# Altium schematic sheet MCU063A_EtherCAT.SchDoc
size 431 x 279 mm; Date: Not shown in title block; ApprovedBy: Not shown in title block; CheckedBy: Not shown in title block; Author: Not shown in title block; CompanyName: Not shown in title block; Engineer: Not shown in title block; Organization: Not shown in title block; Address1: Not shown in title block; Address2: Not shown in title block; Address3: Not shown in title block; Address4: Not shown in title block; DocumentNumber: 8; Revision: Use project parameter SCH_Rev; SheetNumber: 8; SheetTotal: 11; PageSetup: Record=PageOptions¦CenterHorizontal=True¦CenterVertical=True¦PrintScale=1.00¦XCorrection=1.00¦YCorrection=1.00¦PrintKind=0¦BorderSize=5000000¦LeftOffset=0¦BottomOffset=0¦Orientation=2¦PaperLength=1000¦PaperWidth=1000¦Scale=100¦PaperSource=15¦PrintQuality=600¦MediaType=1¦DitherType=10¦PaperKind=Letter¦PrintScaleMode=1
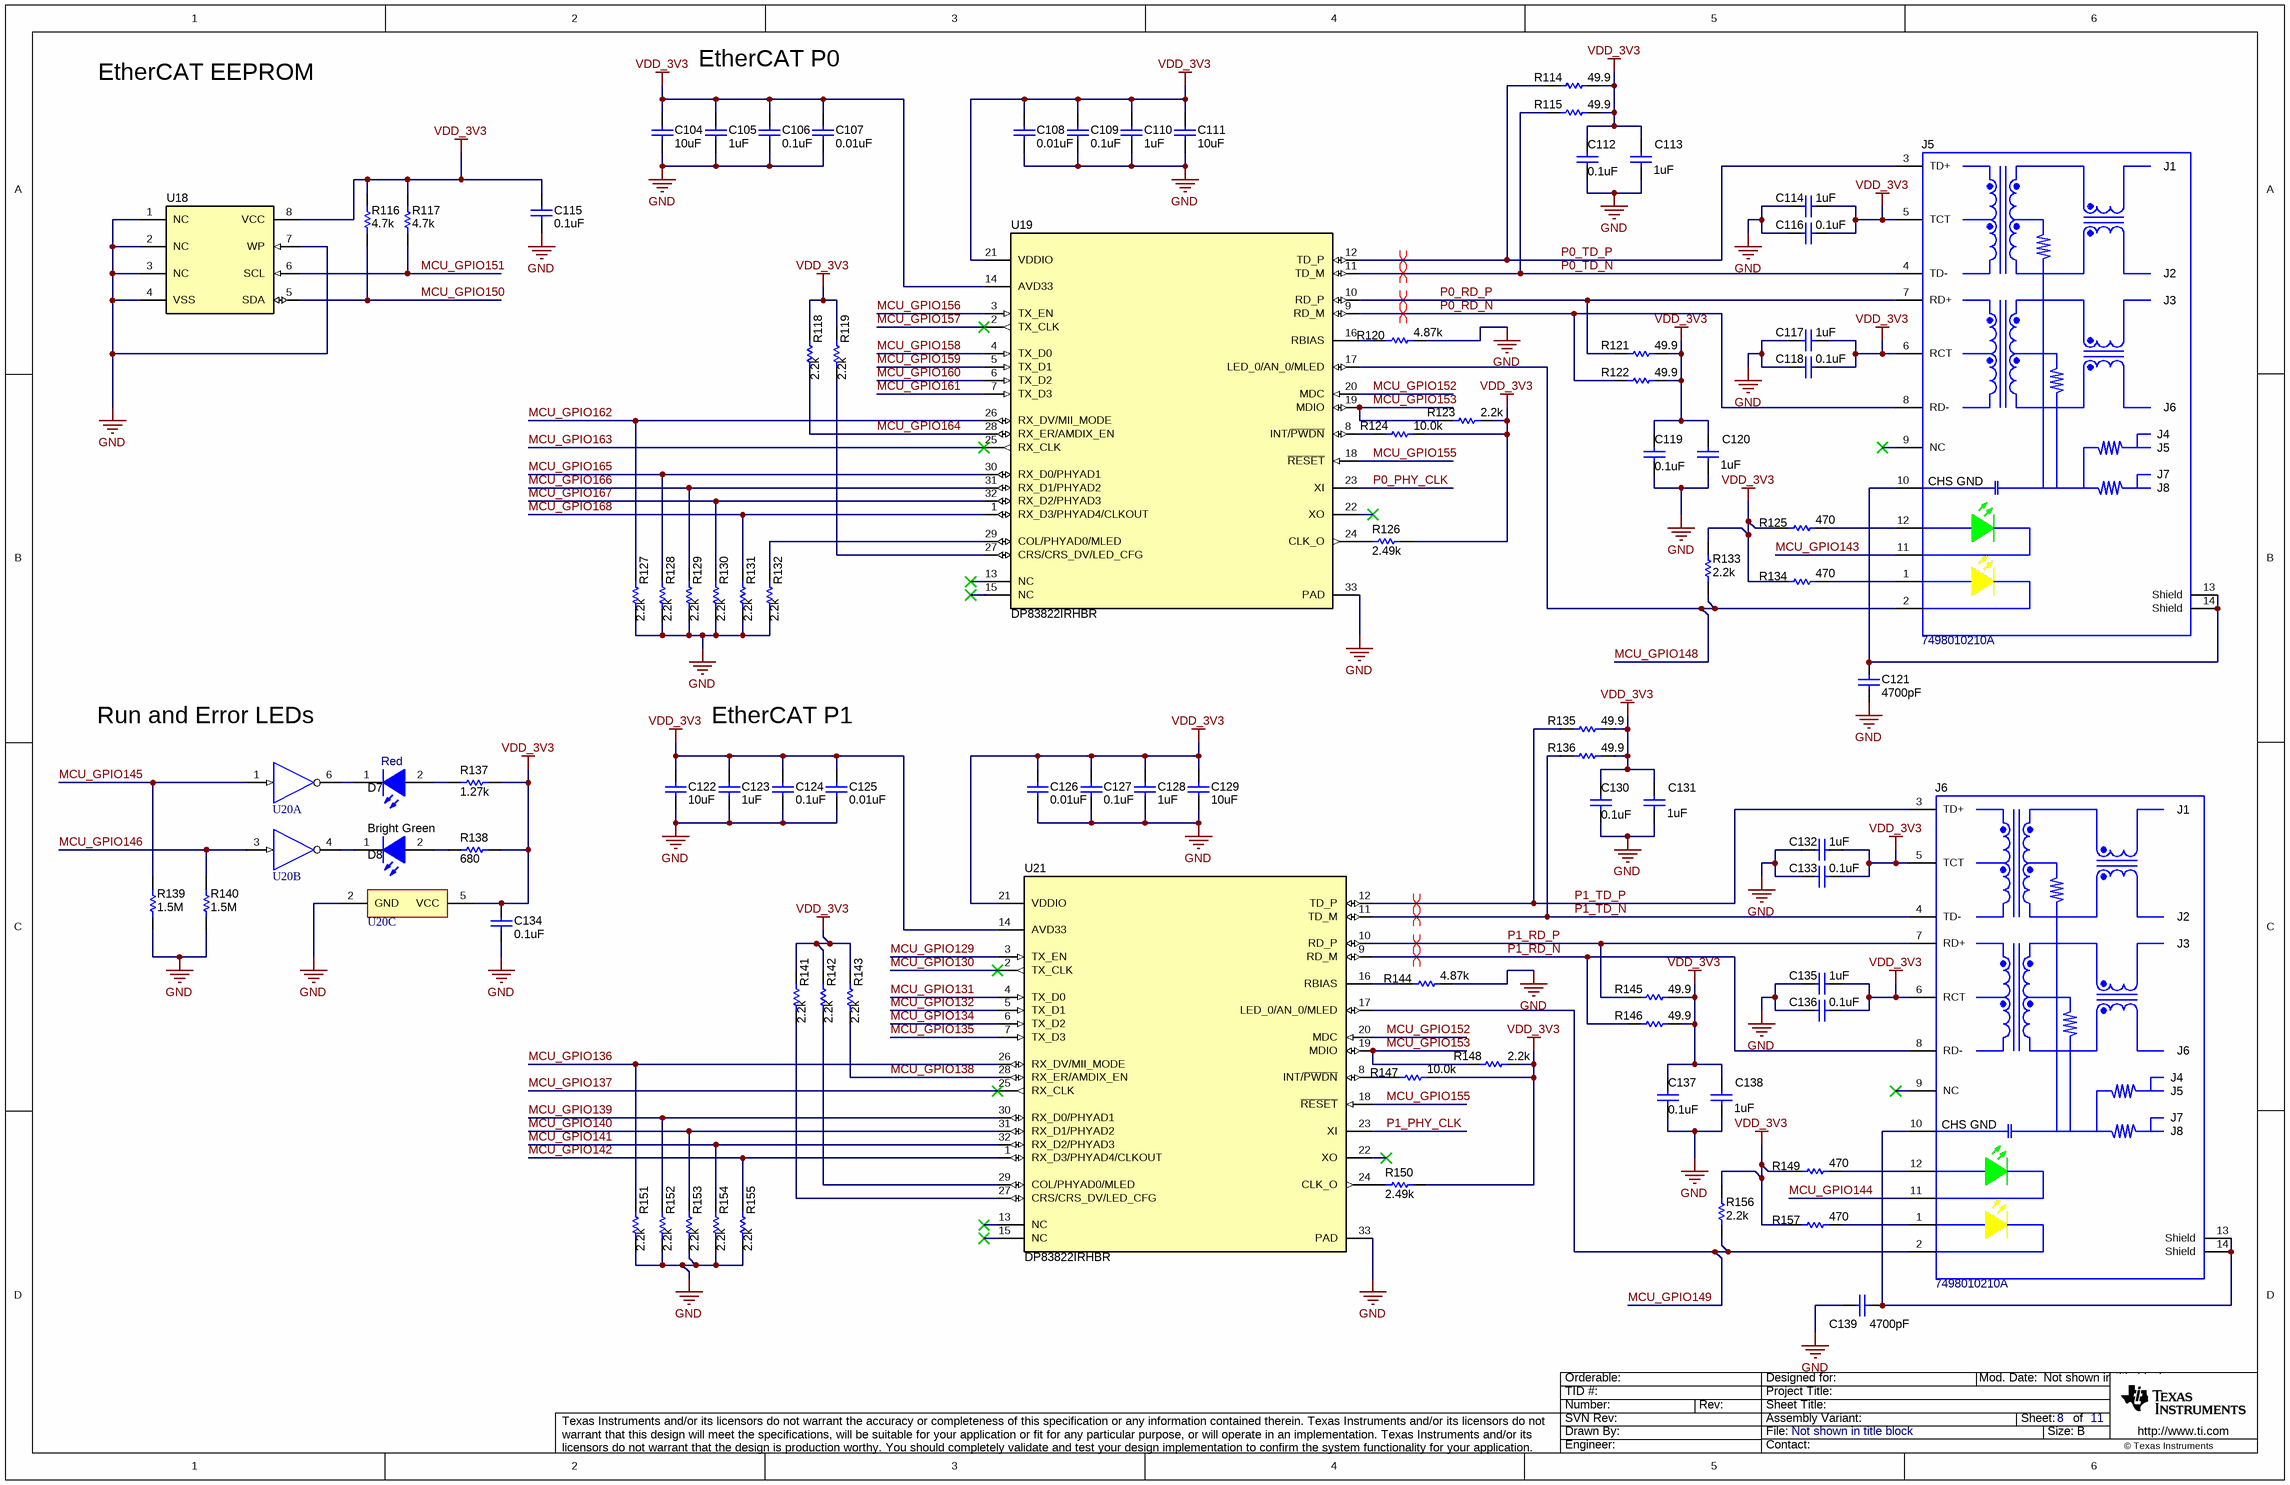
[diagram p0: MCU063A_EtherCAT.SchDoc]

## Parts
C104  ValueDisplayed: 10uF  [0402]  (hidden comment: CL05A106MQ5NUNC)
C105  ValueDisplayed: 1uF  [0402]  (hidden comment: EMK105BJ105KVHF)
C106  ValueDisplayed: 0.1uF  [0402]  (hidden comment: LMK105BJ104KV-F)
C107  ValueDisplayed: 0.01uF  [0402]  (hidden comment: 885012205031)
C108  ValueDisplayed: 0.01uF  [0402]  (hidden comment: 885012205031)
C109  ValueDisplayed: 0.1uF  [0402]  (hidden comment: LMK105BJ104KV-F)
C110  ValueDisplayed: 1uF  [0402]  (hidden comment: EMK105BJ105KVHF)
C111  ValueDisplayed: 10uF  [0402]  (hidden comment: CL05A106MQ5NUNC)
C112  ValueDisplayed: 0.1uF  [0402]  (hidden comment: LMK105BJ104KV-F)
C113  ValueDisplayed: 1uF  [0402]  (hidden comment: EMK105BJ105KVHF)
C114  ValueDisplayed: 1uF  [0402]  (hidden comment: EMK105BJ105KVHF)
C115  ValueDisplayed: 0.1uF  [0402]  (hidden comment: CL05B104KP5NNNC)
C116  ValueDisplayed: 0.1uF  [0402]  (hidden comment: LMK105BJ104KV-F)
C117  ValueDisplayed: 1uF  [0402]  (hidden comment: EMK105BJ105KVHF)
C118  ValueDisplayed: 0.1uF  [0402]  (hidden comment: LMK105BJ104KV-F)
C119  ValueDisplayed: 0.1uF  [0402]  (hidden comment: LMK105BJ104KV-F)
C120  ValueDisplayed: 1uF  [0402]  (hidden comment: EMK105BJ105KVHF)
C121  ValueDisplayed: 4700pF  [1206]  (hidden comment: 12061C472KAT2A)
C122  ValueDisplayed: 10uF  [0402]  (hidden comment: CL05A106MQ5NUNC)
C123  ValueDisplayed: 1uF  [0402]  (hidden comment: EMK105BJ105KVHF)
C124  ValueDisplayed: 0.1uF  [0402]  (hidden comment: LMK105BJ104KV-F)
C125  ValueDisplayed: 0.01uF  [0402]  (hidden comment: 885012205031)
C126  ValueDisplayed: 0.01uF  [0402]  (hidden comment: 885012205031)
C127  ValueDisplayed: 0.1uF  [0402]  (hidden comment: LMK105BJ104KV-F)
C128  ValueDisplayed: 1uF  [0402]  (hidden comment: EMK105BJ105KVHF)
C129  ValueDisplayed: 10uF  [0402]  (hidden comment: CL05A106MQ5NUNC)
C130  ValueDisplayed: 0.1uF  [0402]  (hidden comment: LMK105BJ104KV-F)
C131  ValueDisplayed: 1uF  [0402]  (hidden comment: EMK105BJ105KVHF)
C132  ValueDisplayed: 1uF  [0402]  (hidden comment: EMK105BJ105KVHF)
C133  ValueDisplayed: 0.1uF  [0402]  (hidden comment: LMK105BJ104KV-F)
C134  ValueDisplayed: 0.1uF  [0402]  (hidden comment: CL05B104KP5NNNC)
C135  ValueDisplayed: 1uF  [0402]  (hidden comment: EMK105BJ105KVHF)
C136  ValueDisplayed: 0.1uF  [0402]  (hidden comment: LMK105BJ104KV-F)
C137  ValueDisplayed: 0.1uF  [0402]  (hidden comment: LMK105BJ104KV-F)
C138  ValueDisplayed: 1uF  [0402]  (hidden comment: EMK105BJ105KVHF)
C139  ValueDisplayed: 4700pF  [1206]  (hidden comment: 12061C472KAT2A)
D7  value Red  [WL-SMCW_RED_0805]  (hidden comment: 150080SS75000)
D8  value Bright Green  [WL-SMCW_Green_0805]  (hidden comment: 150080VS75000)
J5  7498010210A  [Wurth_7498010210A]
J6  7498010210A  [Wurth_7498010210A]
R114  ValueDisplayed: 49.9  [0402]  (hidden comment: RC0402FR-0749R9L)
R115  ValueDisplayed: 49.9  [0402]  (hidden comment: RC0402FR-0749R9L)
R116  ValueDisplayed: 4.7k  [0402]  (hidden comment: CRCW04024K70JNED)
R117  ValueDisplayed: 4.7k  [0402]  (hidden comment: CRCW04024K70JNED)
R118  ValueDisplayed: 2.2k  [0201]  (hidden comment: CRCW02012K20JNED)
R119  ValueDisplayed: 2.2k  [0201]  (hidden comment: CRCW02012K20JNED)
R120  ValueDisplayed: 4.87k  [0402]  (hidden comment: CRCW04024K87FKED)
R121  ValueDisplayed: 49.9  [0402]  (hidden comment: RC0402FR-0749R9L)
R122  ValueDisplayed: 49.9  [0402]  (hidden comment: RC0402FR-0749R9L)
R123  ValueDisplayed: 2.2k  [0402]  (hidden comment: CRCW04022K20JNED)
R124  ValueDisplayed: 10.0k  [0402]  (hidden comment: RC0402FR-0710KL)
R125  ValueDisplayed: 470  [0603]  (hidden comment: CRCW0603470RJNEA)
R126  ValueDisplayed: 2.49k  [0402]  (hidden comment: CRCW04022K49FKED)
R127  ValueDisplayed: 2.2k  [0201]  (hidden comment: CRCW02012K20JNED)
R128  ValueDisplayed: 2.2k  [0201]  (hidden comment: CRCW02012K20JNED)
R129  ValueDisplayed: 2.2k  [0201]  (hidden comment: CRCW02012K20JNED)
R130  ValueDisplayed: 2.2k  [0201]  (hidden comment: CRCW02012K20JNED)
R131  ValueDisplayed: 2.2k  [0201]  (hidden comment: CRCW02012K20JNED)
R132  ValueDisplayed: 2.2k  [0201]  (hidden comment: CRCW02012K20JNED)
R133  ValueDisplayed: 2.2k  [0402]  (hidden comment: CRCW04022K20JNED)
R134  ValueDisplayed: 470  [0603]  (hidden comment: CRCW0603470RJNEA)
R135  ValueDisplayed: 49.9  [0402]  (hidden comment: RC0402FR-0749R9L)
R136  ValueDisplayed: 49.9  [0402]  (hidden comment: RC0402FR-0749R9L)
R137  ValueDisplayed: 1.27k  [0402]  (hidden comment: CRCW04021K27FKED)
R138  ValueDisplayed: 680  [0402]  (hidden comment: CRCW0402680RJNED)
R139  ValueDisplayed: 1.5M  [0402]  (hidden comment: CRCW04021M50JNED)
R140  ValueDisplayed: 1.5M  [0402]  (hidden comment: CRCW04021M50JNED)
R141  ValueDisplayed: 2.2k  [0201]  (hidden comment: CRCW02012K20JNED)
R142  ValueDisplayed: 2.2k  [0201]  (hidden comment: CRCW02012K20JNED)
R143  ValueDisplayed: 2.2k  [0201]  (hidden comment: CRCW02012K20JNED)
R144  ValueDisplayed: 4.87k  [0402]  (hidden comment: CRCW04024K87FKED)
R145  ValueDisplayed: 49.9  [0402]  (hidden comment: RC0402FR-0749R9L)
R146  ValueDisplayed: 49.9  [0402]  (hidden comment: RC0402FR-0749R9L)
R147  ValueDisplayed: 10.0k  [0402]  (hidden comment: RC0402FR-0710KL)
R148  ValueDisplayed: 2.2k  [0402]  (hidden comment: CRCW04022K20JNED)
R149  ValueDisplayed: 470  [0603]  (hidden comment: CRCW0603470RJNEA)
R150  ValueDisplayed: 2.49k  [0402]  (hidden comment: CRCW04022K49FKED)
R151  ValueDisplayed: 2.2k  [0201]  (hidden comment: CRCW02012K20JNED)
R152  ValueDisplayed: 2.2k  [0201]  (hidden comment: CRCW02012K20JNED)
R153  ValueDisplayed: 2.2k  [0201]  (hidden comment: CRCW02012K20JNED)
R154  ValueDisplayed: 2.2k  [0201]  (hidden comment: CRCW02012K20JNED)
R155  ValueDisplayed: 2.2k  [0201]  (hidden comment: CRCW02012K20JNED)
R156  ValueDisplayed: 2.2k  [0402]  (hidden comment: CRCW04022K20JNED)
R157  ValueDisplayed: 470  [0603]  (hidden comment: CRCW0603470RJNEA)
U18  CAT24C16WI-GT3  [SOIC-8]  (value not drawn)
U19  DP83822IRHBR  [RHB0032B]
U20  SN74LVC2G06DBVR  [DBV0006A_N]  (value not drawn)  (parts A,B,C of 3)
U21  DP83822IRHBR  [RHB0032B]

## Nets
GND: C104.2 C105.2 C106.2 C107.2 C108.2 C109.2 C110.2 C111.2 C112.2 C113.2 C114.1 C115.2 C116.1 C117.1 C118.1 C119.2 C120.2 C121.1 C122.2 C123.2 C124.2 C125.2 C126.2 C127.2 C128.2 C129.2 C130.2 C131.2 C132.1 C133.1 C134.2 C135.1 C136.1 C137.2 C138.2 C139.1 R120.2 R127.1 R128.1 R129.1 R130.1 R131.1 R132.1 R139.2 R140.2 R144.2 R151.1 R152.1 R153.1 R154.1 R155.1 U18.1(NC) U18.2(NC) U18.3(NC) U18.4(VSS) U18.7(WP) U19.33(PAD) U20.2(GND) U21.33(PAD)
VDD_3V3: C104.1 C105.1 C106.1 C107.1 C108.1 C109.1 C110.1 C111.1 C112.1 C113.1 C114.2 C115.1 C116.2 C117.2 C118.2 C119.1 C120.1 C122.1 C123.1 C124.1 C125.1 C126.1 C127.1 C128.1 C129.1 C130.1 C131.1 C132.2 C133.2 C134.1 C135.2 C136.2 C137.1 C138.1 J5.5(TCT) J5.6(RCT) J6.5(TCT) J6.6(RCT) R114.2 R115.2 R116.2 R117.2 R118.2 R119.2 R121.2 R122.2 R123.1 R124.2 R125.1 R126.1 R133.2 R134.1 R135.2 R136.2 R137.2 R138.1 R141.2 R142.2 R143.2 R145.2 R146.2 R147.2 R148.1 R149.1 R150.1 R156.2 R157.1 U18.8(VCC) U19.14(AVD33) U19.21(VDDIO) U20.5(VCC) U21.14(AVD33) U21.21(VDDIO)
MCU_GPIO129: U21.3(TX_EN)
MCU_GPIO130: U21.2(TX_CLK)
MCU_GPIO131: U21.4(TX_D0)
MCU_GPIO132: U21.5(TX_D1)
MCU_GPIO134: U21.6(TX_D2)
MCU_GPIO135: U21.7(TX_D3)
MCU_GPIO136: R151.2 U21.26(RX_DV/MII_MODE)
MCU_GPIO137: U21.25(RX_CLK)
MCU_GPIO138: R143.1 U21.28(RX_ER/AMDIX_EN)
MCU_GPIO139: R152.2 U21.30(RX_D0/PHYAD1)
MCU_GPIO140: R153.2 U21.31(RX_D1/PHYAD2)
MCU_GPIO141: R154.2 U21.32(RX_D2/PHYAD3)
MCU_GPIO142: R155.2 U21.1(RX_D3/PHYAD4/CLKOUT)
MCU_GPIO143: J5.11(LEFT_LED_CATHODE)
MCU_GPIO144: J6.11(LEFT_LED_CATHODE)
MCU_GPIO145: R139.1 U20.1(1A)
MCU_GPIO146: R140.1 U20.3(2A)
MCU_GPIO148: J5.2(RIGHT_LED_CATHODE) R133.1 U19.17(LED_0/AN_0/MLED)
MCU_GPIO149: J6.2(RIGHT_LED_CATHODE) R156.1 U21.17(LED_0/AN_0/MLED)
MCU_GPIO150: R116.1 U18.5(SDA)
MCU_GPIO151: R117.1 U18.6(SCL)
MCU_GPIO152: U19.20(MDC) U21.20(MDC)
MCU_GPIO153: R123.2 R148.2 U19.19(MDIO) U21.19(MDIO)
MCU_GPIO155: U19.18(~{RESET}) U21.18(~{RESET})
MCU_GPIO156: U19.3(TX_EN)
MCU_GPIO157: U19.2(TX_CLK)
MCU_GPIO158: U19.4(TX_D0)
MCU_GPIO159: U19.5(TX_D1)
MCU_GPIO160: U19.6(TX_D2)
MCU_GPIO161: U19.7(TX_D3)
MCU_GPIO162: R127.2 U19.26(RX_DV/MII_MODE)
MCU_GPIO163: U19.25(RX_CLK)
MCU_GPIO164: R118.1 U19.28(RX_ER/AMDIX_EN)
MCU_GPIO165: R128.2 U19.30(RX_D0/PHYAD1)
MCU_GPIO166: R129.2 U19.31(RX_D1/PHYAD2)
MCU_GPIO167: R130.2 U19.32(RX_D2/PHYAD3)
MCU_GPIO168: R131.2 U19.1(RX_D3/PHYAD4/CLKOUT)
P0_PHY_CLK: U19.23(XI)
P0_RD_N: J5.8(RD-) R122.1 U19.9(RD_M)
P0_RD_P: J5.7(RD+) R121.1 U19.10(RD_P)
P0_TD_N: J5.4(TD-) R115.1 U19.11(TD_M)
P0_TD_P: J5.3(TD+) R114.1 U19.12(TD_P)
P1_PHY_CLK: U21.23(XI)
P1_RD_N: J6.8(RD-) R146.1 U21.9(RD_M)
P1_RD_P: J6.7(RD+) R145.1 U21.10(RD_P)
P1_TD_N: J6.4(TD-) R136.1 U21.11(TD_M)
P1_TD_P: J6.3(TD+) R135.1 U21.12(TD_P)
NetC121_2: C121.2 J5.10(CHS_GND) J5.13(Shield) J5.14(Shield)
NetC139_2: C139.2 J6.10(CHS_GND) J6.13(Shield) J6.14(Shield)
NetD7_1: D7.1(K) U20.6(1Y)
NetD7_2: D7.2(A) R137.1
NetD8_1: D8.1(K) U20.4(2Y)
NetD8_2: D8.2(A) R138.2
NetJ5_1: J5.1(RIGHT_LED_ANODE) R134.2
NetJ5_12: J5.12(LEFT_LED_ANODE) R125.2
NetJ6_1: J6.1(RIGHT_LED_ANODE) R157.2
NetJ6_12: J6.12(LEFT_LED_ANODE) R149.2
NetR119_1: R119.1 U19.27(CRS/CRS_DV/LED_CFG)
NetR120_1: R120.1 U19.16(RBIAS)
NetR124_1: R124.1 U19.8(INT/~{PWDN})
NetR126_2: R126.2 U19.24(CLK_O)
NetR132_2: R132.2 U19.29(COL/PHYAD0/MLED)
NetR141_1: R141.1 U21.27(CRS/CRS_DV/LED_CFG)
NetR142_1: R142.1 U21.29(COL/PHYAD0/MLED)
NetR144_1: R144.1 U21.16(RBIAS)
NetR147_1: R147.1 U21.8(INT/~{PWDN})
NetR150_2: R150.2 U21.24(CLK_O)

Not connected (* = marked no-connect by the designer): J5 9(NC)*; J6 9(NC)*; U19 13(NC)* 15(NC)* 22(XO)*; U21 13(NC)* 15(NC)* 22(XO)*

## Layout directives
differential pair: P0_RD_N, P0_RD_P, P0_TD_N, P0_TD_P, P1_RD_N, P1_RD_P, P1_TD_N, P1_TD_P

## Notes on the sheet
- EtherCAT EEPROM
- EtherCAT P0
- Run and Error LEDs
- EtherCAT P1

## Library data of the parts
C104 C111 C122 C129 = CMP-0006340-2: CAP, CERM, 10 uF, 6.3 V, +/- 20%, X5R, 0402; Manufacturer: Samsung Electro-Mechanics; TaMin_C: -55°C; Polarized: N; SizeAreaWB_mm2: 3; Value1: Unknown; U/M: EA; Value: 10uF; TaMax_C: 85°C; SizeZ_mm: 0.6; SizeX_mm: 1; SizeY_mm: 0.5; Value2: 6.3V; Cap_F: 10µF; AEC Category: Q200
C105 C110 C113 C114 C117 C120 C123 C128 C131 C132 C135 C138 = CMP-0006347-2: CAP, CERM, 1 uF, 16 V, +/- 10%, X5R, 0402; Manufacturer: Taiyo Yuden; TaMin_C: -55°C; Polarized: N; SizeAreaWB_mm2: 3; Value1: Unknown; U/M: EA; Value: 1uF; TaMax_C: 85°C; SizeZ_mm: 0.6; SizeX_mm: 1; SizeY_mm: 0.5; Value2: 16V; Cap_F: 1µF; AEC Category: Q200
C106 C109 C112 C116 C118 C119 C124 C127 C130 C133 C136 C137 = CMP-0064930-2: CAP, CERM, 0.1 uF, 10 V,+/- 10%, X5R, 0402; Manufacturer: Taiyo Yuden; TaMin_C: -55°C; Polarized: N; SizeAreaWB_mm2: 3; Value1: Unknown; U/M: EA; Value: 0.1uF; TaMax_C: 85°C; SizeZ_mm: 0.6; SizeX_mm: 1; SizeY_mm: 0.5; Value2: 10V; Cap_F: 100nF; AEC Category: Q200
C107 C108 C125 C126 = CMP-0006227-2: CAP, CERM, 0.01 uF, 16 V, +/- 10%, X7R, 0402; Manufacturer: Wurth Elektronik; TaMin_C: -55°C; Polarized: N; SizeAreaWB_mm2: 3; Value1: Unknown; U/M: EA; Value: 0.01uF; TaMax_C: 125°C; SizeZ_mm: 0.6; SizeX_mm: 1; SizeY_mm: 0.5; Value2: 16V; Cap_F: 10nF; AEC Category: Q200
C115 C134 = CMP-0006343-2: CAP, CERM, 0.1 uF, 10 V, +/- 10%, X7R, 0402; Manufacturer: Samsung Electro-Mechanics; Polarized: N; Value: 0.1uF; U/M: EA; Cap_F: 100nF; Value1: Unknown; VDC_V: 10V; TaMin_C: -55°C; TaMax_C: 125°C; AEC Category: Q200; SizeArea_mm2: 0.5; SizeAreaWB_mm2: 3; SizeX_mm: 1; SizeZ_mm: 0.6
C121 C139 = CMP-0008501-2: CAP, CERM, 4700 pF, 100 V, +/- 10%, X7R, 1206; Manufacturer: AVX; TaMin_C: -55°C; ESR_ohm: 1.78d; Polarized: N; SizeAreaWB_mm2: 10.92; Value1: 0.178 ohm; U/M: EA; Value: 4700pF; TaMax_C: 125°C; SizeZ_mm: 1.35; SizeX_mm: 3.2; SizeY_mm: 1.6; Value2: 100V; SizeArea_mm2: 5.12; Cap_F: 4.7nF; AEC Category: Q200
D7 = CMP-0002951-3: LED, Red, SMD; Manufacturer: Wurth Elektronik; Type: AlInGaP; Vf_V: 1.9V; Io_A: 30mA; Vr_V: 5V; Ir_A: 25µA; Tjmax_C: 85°C; Power_TotalModule: 72mW; Value1: 0.072W; Angle: 140
D8 = CMP-0002960-2: LED, Bright Green, SMD; Manufacturer: Wurth Elektronik; Type: AlInGaP; Vf_V: 2V; Io_A: 20mA; Vr_V: 5V; Tjmax_C: 85°C; Power_TotalModule: 72mW; Value1: 0.072W; Angle: 140; U/M: EA
J5 J6 = CMP-0086350-1: Connector, RJ45, 1x1, Gold, R/A, SMT; Manufacturer: Wurth Elektronik; Row_Count: 1; Gender: Female
R114 R115 R121 R122 R135 R136 R145 R146 = CMP-0026738-1: RES, 49.9, 1%, 0.063 W, 0402; Manufacturer: Yageo America; Power_W: 63mW; TempCo: 100 ppm/C; Value_Code: 49R9; U/M: EA; Value: 49.9; EIA_Code: E96; SizeX_mm: 1; SizeY_mm: 0.5; SizeZ_mm: 0.6; Value2: 0.063W; AEC Qualified: N; VDC_V: 50V; AEC Category: Q200
R116 R117 = CMP-0026938-5: RES, 4.7 k, 5%, 0.063 W, AEC-Q200 Grade 0, 0402; Manufacturer: Vishay-Dale; Power_W: 63mW; TempCo: 200 ppm/C; Value_Code: 4k70; Value: 4.7k; EIA_Code: E24; SizeX_mm: 1; SizeY_mm: 0.5; SizeZ_mm: 0.6; Value2: 0.063W; AEC Qualified: Y; VDC_V: 50V; AEC Category: Q200; AEC Grade: 0
R118 R119 R127-R132 R141-R143 R151-R155 = CMP-0027010-2: RES, 2.2 k, 5%, 0.05 W, 0201; Manufacturer: Vishay-Dale; Power_W: 50mW; TempCo: 200 ppm/C; Value_Code: 2k20; Value: 2.2k; EIA_Code: E24; SizeX_mm: 0.6; SizeY_mm: 0.3; SizeZ_mm: 0.26; Value2: 0.05W; SizeArea_mm2: 0.18; AEC Qualified: N; VDC_V: 30V; AEC Category: Q200
R120 R144 = CMP-0026413-2: RES, 4.87 k, 1%, 0.063 W, AEC-Q200 Grade 0, 0402; Manufacturer: Vishay-Dale; Power_W: 63mW; TempCo: 100 ppm/C; Value_Code: 4k87; Value: 4.87k; EIA_Code: E96; SizeX_mm: 1; SizeY_mm: 0.5; SizeZ_mm: 0.6; Value2: 0.063W; AEC Qualified: Y; VDC_V: 50V; AEC Category: Q200; AEC Grade: 0
R123 R133 R148 R156 = CMP-0026890-5: RES, 2.2 k, 5%, 0.063 W, AEC-Q200 Grade 0, 0402; Manufacturer: Vishay-Dale; Power_W: 63mW; TempCo: 200 ppm/C; Value_Code: 2k20; Value: 2.2k; EIA_Code: E24; SizeX_mm: 1; SizeY_mm: 0.5; SizeZ_mm: 0.6; Value2: 0.063W; AEC Qualified: Y; VDC_V: 50V; AEC Category: Q200; AEC Grade: 0
R124 R147 = CMP-0078669-1: RES, 10.0 k, 1%, 0.063 W, 0402; Manufacturer: Yageo America; Power_W: 63mW; Green_Lifecycle: Active; TempCo: 100 ppm/C; Value_Code: 10k0; Green_REACh: Passed; Value: 10.0k; EIA_Code: E96; Res_ohm: 10k; SizeX_mm: 1; SizeY_mm: 0.5; SizeZ_mm: 0.6; Value2: 0.063W; AEC Qualified: N; AEC Category: Q200
R125 R134 R149 R157 = CMP-0025813-4: RES, 470, 5%, 0.1 W, AEC-Q200 Grade 0, 0603; Manufacturer: Vishay-Dale; Power_W: 100mW; TempCo: 200 ppm/C; Value_Code: 470R; Value: 470; EIA_Code: E24; SizeX_mm: 1.6; SizeY_mm: 0.8; SizeZ_mm: 1; Value2: 0.1W; SizeArea_mm2: 1.28; AEC Qualified: Y; VDC_V: 75V; AEC Category: Q200; AEC Grade: 0
R126 R150 = CMP-0026237-2: RES, 2.49 k, 1%, 0.063 W, AEC-Q200 Grade 0, 0402; Manufacturer: Vishay-Dale; Power_W: 63mW; TempCo: 100 ppm/C; Value_Code: 2k49; Value: 2.49k; EIA_Code: E96; SizeX_mm: 1; SizeY_mm: 0.5; SizeZ_mm: 0.6; Value2: 0.063W; AEC Qualified: Y; VDC_V: 50V; AEC Category: Q200; AEC Grade: 0
R137 = CMP-0026081-3: RES, 1.27 k, 1%, 0.063 W, AEC-Q200 Grade 0, 0402; Manufacturer: Vishay-Dale; Power_W: 63mW; TempCo: 100 ppm/C; Value_Code: 1k27; Value: 1.27k; EIA_Code: E96; SizeX_mm: 1; SizeY_mm: 0.5; SizeZ_mm: 0.6; Value2: 0.063W; AEC Qualified: Y; VDC_V: 50V; AEC Category: Q200; AEC Grade: 0
R138 = CMP-0026962-3: RES, 680, 5%, 0.063 W, AEC-Q200 Grade 0, 0402; Manufacturer: Vishay-Dale; Value: 680; Value_Code: 680R; Power_W: 63mW; Value2: 0.063W; VDC_V: 50V; TempCo: 200 ppm/C; EIA_Code: E24; AEC Category: Q200; AEC Qualified: Y; AEC Grade: 0; SizeArea_mm2: 0.5; SizeX_mm: 1; SizeZ_mm: 0.6
R139 R140 = CMP-0026863-2: RES, 1.5 M, 5%, 0.063 W, AEC-Q200 Grade 0, 0402; Manufacturer: Vishay-Dale; Power_W: 63mW; TempCo: 200 ppm/C; Value_Code: 1M50; Value: 1.5Meg; EIA_Code: E24; SizeX_mm: 1; SizeY_mm: 0.5; SizeZ_mm: 0.6; Value2: 0.063W; AEC Qualified: Y; VDC_V: 50V; AEC Category: Q200; AEC Grade: 0
U18 = CMP-0082059-1: 16 Kb I2C EEPROM Serial, SOIC-8; Manufacturer: ON Semiconductor; SizeArea_mm2: 29.351; SizeAreaWB_mm2: 55.131; SizeY_mm: 4.9; SizeZ_mm: 1.75; SizeX_mm: 5.99
U19 U21 = CMP-0076010-3: Robust, Low Power 10/100 Ethernet Physical Layer Transceiver, RHB0032B (VQFN-32); Alternate PartNumber: DP83822IRHBT; Manufacturer: Texas Instruments; SizeZ_mm: 1.0; SizeX_mm: 5.0; SizeArea_mm2: 25.0; CompType: IC; SizeAreaWB_mm2: 49.0; AEC Category: Q200; AEC Qualified: N
U20 = CMP-0051777-1: Dual Inverter Buffer/Driver with Open-Drain Output, DBV0006A, LARGE T&R; Manufacturer: Texas Instruments; Schmitt Trigger: No; Logic: Inverting; F @ Nom Voltage(Max)(Mhz): 150; VCC(Max)(V): 5.5; Rating: Catalog; Sub-Family: Inverting Buffer/Driver; Technology Family: LVC; VCC(Min)(V): 1.65; Voltage(Nom)(V): 1.8,2.5,3.3,5; Output Drive (IOL/IOH)(Max)(mA): 32/-32; Output Type: CMOS; ICC @ Nom Voltage(Max)(mA): 0.01; Bits(#): 2; tpd @ Nom Voltage(Max)(ns): 8.2,4.4,3.9,3.4; Input Type: CMOS/TTL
